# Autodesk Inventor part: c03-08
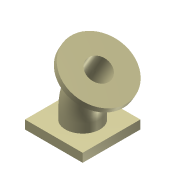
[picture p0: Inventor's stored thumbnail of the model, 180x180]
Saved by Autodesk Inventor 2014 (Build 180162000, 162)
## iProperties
Created: 2011-11
Part Number: c03-08
Material: Iron, Cast
Document SubType Name: Modeling
Designer: Thom Tremblay
Density: 7.25 g/cm^3
Mass: 1087.5 g
Surface Area: 260 cm^2
Volume: 150 cm^3
Appearance: Nylon 6
Author: Thom Tremblay
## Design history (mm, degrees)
sketch "Sketch1"
  geometry: L1 (50, -50)-(-50, -50); L2 (-50, -50)-(-50, 50); L3 (-50, 50)-(50, 50); L4 (50, 50)-(50, -50); C1 r 20 at (0, 0); C2 r 30 at (0, 0); 3 further points
  constraints: 8 end point, 2 centre point, 2 coincident, 2 midpoint, 2 parallel, 2 perpendicular, 1 horizontal, 1 horizontal alignment, 1 vertical alignment
  dimensions: "d0" = 100 distance of L2.end L3.end; "d3" = 40 diameter of C1; "d4" = 10 radial gap between concentric circles of C2 C1
extrude "Extrusion1" new body sketch "Sketch1" distance "d1" = 15; taper "d2" = 0 deg
sketch "Sketch2"
  geometry: L1 (0, 0)-(0, 30); L2 (12.794, 77.746)-(27.794, 103.727); A1 r 95.493 centre (95.493, 30) between (12.794, 77.746) and (0, 30)
  constraints: 4 end point, 2 point on circle, 2 tangent, 1 centre point, 1 vertical
  dimensions: "d5" = 30 distance of L1.start L1.end; "d7" = 50 dimension on A1; "d9" = 30 distance of L2.start L2.end; "d10" = 30 deg angle of L2 L1
sketch "Sketch3"
  geometry: L1 (12.794, 77.746)-(27.794, 103.727) reference; L2 (27.794, 103.727)-(75.425, 76.227); L3 (75.425, 76.227)-(70.425, 67.567); L4 (70.425, 67.567)-(22.794, 95.067); L5 (22.794, 95.067)-(27.794, 103.727); 2 further points
  constraints: 8 end point, 2 parallel, 2 perpendicular
  dimensions: "d11" = 110 diameter of L3 L5; "d13" = 10 distance between parallel lines of L2 L4
revolve "Revolution1" sketch "Sketch3" stored, may be unused: angle "d14" = 90 deg
sweep "Sweep1" dims "d15" = 0
sweep "Sweep2" dims "d16" = 0
body "Solid1"
